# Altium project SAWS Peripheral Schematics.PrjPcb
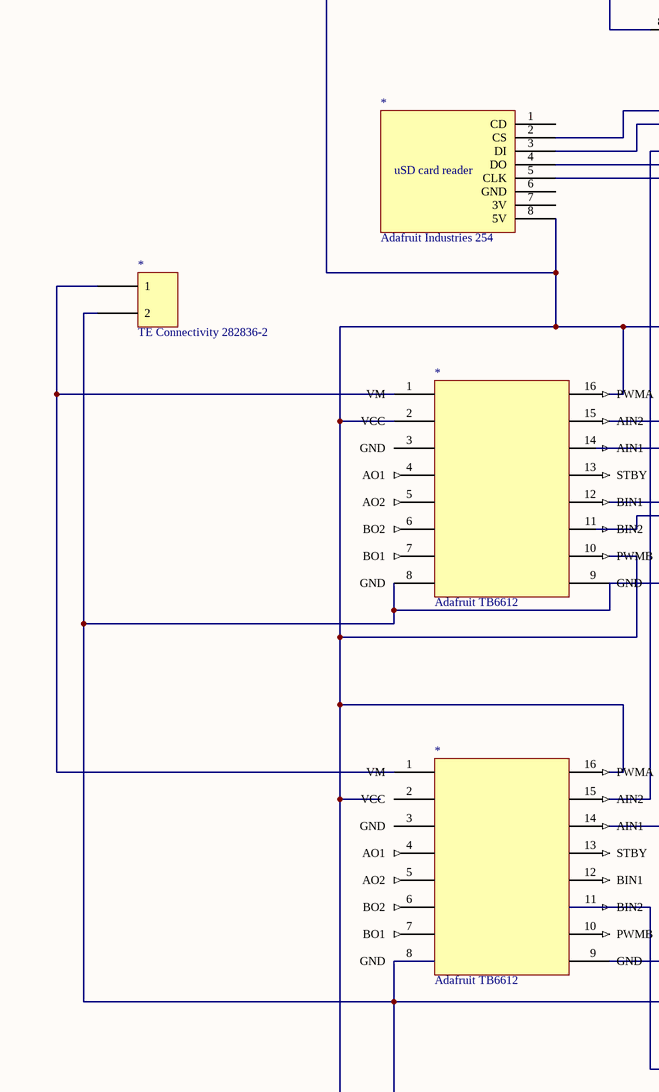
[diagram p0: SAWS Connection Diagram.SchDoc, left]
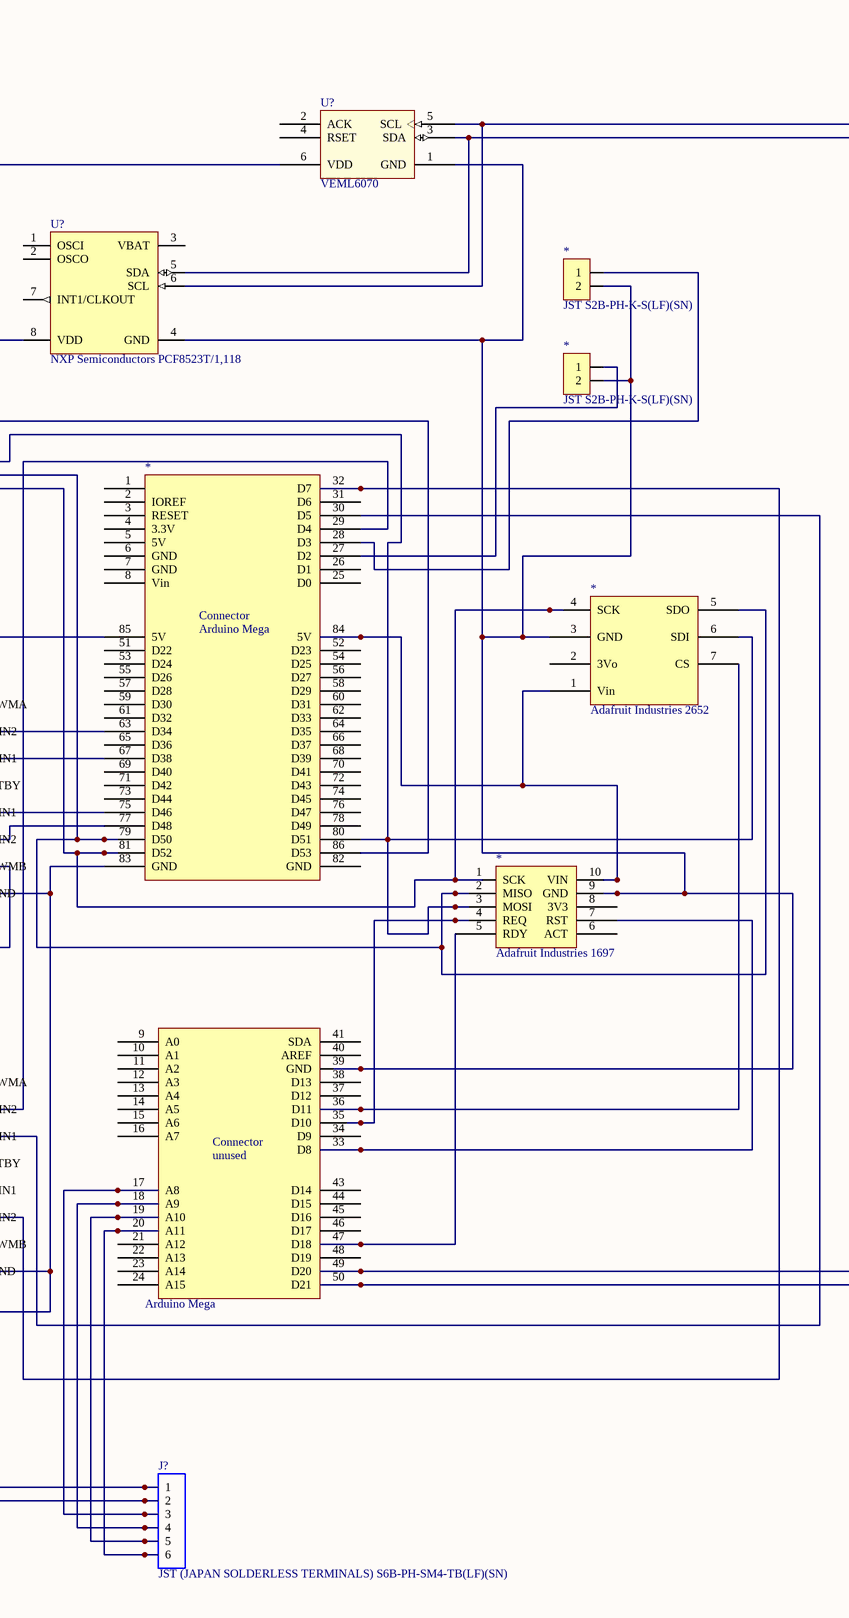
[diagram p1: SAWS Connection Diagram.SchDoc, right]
1 sheet, 12 parts. Net scope: global (net labels, ports and power ports of the same name join across sheets).

## Sheet SAWS Connection Diagram.SchDoc
size 500 x 500 mm

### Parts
(Parts that share a designator on the sheet are numbered #1, #2 ... from top to bottom, then left to right.)
*#1  JST S2B-PH-K-S(LF)(SN)  [PCBComponent_1 - duplicate]
*#2  JST S2B-PH-K-S(LF)(SN)  [PCBComponent_1 - duplicate]
*#3  Adafruit Industries 254  [PCB-14uusre4tcuerloricup-1]
*#4  TE Connectivity 282836-2  [PCB-0kdx5sneyudsmu18l6zv-1]
*#5  Adafruit Industries 2652  [PCB-8cpanwn2r2nbal49d52i-1]
*#6  Adafruit TB6612  [PCB-i53bh64vexzah4n4868h-1]
*#7  Arduino Mega  [TFT_Shield_MEGA]
*#8  Adafruit Industries 1697  [PCB-jbwx2r95ohr5pnaey095-1]
*#9  Adafruit TB6612  [PCB-i53bh64vexzah4n4868h-1]
J?  JST (JAPAN SOLDERLESS TERMINALS) S6B-PH-SM4-TB(LF)(SN)  [PCB-643062-1]
U?#1  VEML6070  [PCB-p4pozrsuowobialt3zsg-1]
U?#2  NXP Semiconductors PCF8523T/1,118  [PCB-1019860-1]

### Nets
GND: *#6.4(GND) *#6.7(GND) *#9.4(GND) *#9.7(GND)
Net*#1_1: *#1.1 *#7.28(D3)
Net*#1_2: *#1.2 *#2.2 *#5.3(GND) *#7.39(GND) *#8.9(GND) U?#1.1(GND) U?#2.4(GND)
Net*#2_1: *#2.1 *#7.27(D2)
Net*#3_2: *#3.2(CS) *#7.86(D53)
Net*#3_3: *#3.3(DI) *#5.6(SDI) *#7.80(D51) *#8.3(MOSI)
Net*#3_4: *#3.4(DO) *#5.5(SDO) *#7.79(D50) *#8.2(MISO)
Net*#3_5: *#3.5(CLK) *#5.4(SCK) *#7.81(D52) *#8.1(SCK)
Net*#3_8: *#3.8(5V) *#7.85(5V) J?.1 U?#1.6(VDD) U?#2.8(VDD)
Net*#4_2: *#4.2 *#7.83(GND) *#9.8(GND) J?.2
Net*#5_1: *#5.1(Vin) *#7.84(5V) *#8.10(VIN)
Net*#5_7: *#5.7(CS) *#7.36(D11)
Net*#7_17: *#7.17(A8) J?.3
Net*#7_18: *#7.18(A9) J?.4
Net*#7_19: *#7.19(A10) J?.5
Net*#7_20: *#7.20(A11) J?.6
Net*#7_32: *#7.32(D7) *#9.11(BIN2)
Net*#7_33: *#7.33(D8) *#8.7(RST)
Net*#7_35: *#7.35(D10) *#8.4(REQ)
Net*#7_47: *#7.47(D18) *#8.5(RDY)
Net*#7_49: *#7.49(D20) U?#1.3(SDA) U?#2.5(SDA)
Net*#7_50: *#7.50(D21) U?#1.5(SCL) U?#2.6(SCL)

Not connected (* = marked no-connect by the designer): *#3 1(CD) 6(GND) 7(3V); *#4 1; *#5 2(3Vo); *#6 1(VM) 2(VCC) 3(GND) 5(AO2) 6(BO2) 8(GND) 9(GND) 10(PWMB) 11(BIN2) 12(BIN1) 13(STBY) 14(AIN1) 15(AIN2) 16(PWMA); *#7 1 2(IOREF) 3(RESET) 4(3.3V) 5(5V) 6(GND) 7(GND) 8(Vin) 9(A0) 10(A1) 11(A2) 12(A3) 13(A4) 14(A5) 15(A6) 16(A7) 21(A12) 22(A13) 23(A14) 24(A15) 25(D0) 26(D1) 29(D4) 30(D5) 31(D6) 34(D9) 37(D12) 38(D13) 40(AREF) 41(SDA) 43(D14) 44(D15) 45(D16) 46(D17) 48(D19) 51(D22) 52(D23) 53(D24) 54(D25) 55(D26) 56(D27) 57(D28) 58(D29) 59(D30) 60(D31) 61(D32) 62(D33) 63(D34) 64(D35) 65(D36) 66(D37) 67(D38) 68(D39) 69(D40) 70(D41) 71(D42) 72(D43) 73(D44) 74(D45) 75(D46) 76(D47) 77(D48) 78(D49) 82(GND); *#8 6(ACT) 8(3V3); *#9 1(VM) 2(VCC) 3(GND) 5(AO2) 6(BO2) 9(GND) 10(PWMB) 12(BIN1) 13(STBY) 14(AIN1) 15(AIN2) 16(PWMA); U?#1 2(ACK) 4(RSET); U?#2 1(OSCI) 2(OSCO) 3(VBAT) 7(INT1/CLKOUT)

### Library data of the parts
*#1 *#2 = S2B-PH-K-S(LF)(SN): JST S2B-PH-K-S (LF)(SN) Multi-pin Connector, Angled Series PH Number of pins: 2 Nominal current: 2 A; Voltage Rating (AC): 100 V; Lead-Free Status: Lead Free; Pin Pitch: 2.00 mm; Number of Contacts: 2; Gender: Male; Insulation Resistance: 1.00 GΩ; Current Rating: 2.00 A
*#3 = 254: Roll Pin Punch 5/32 x 4-1/2 Inch Steel - GR0191303; Manufacturer Part Number: 254
*#4 = 282836-2: Wire to Board 2 Position 5 mm Pitch 30-16 AWG Euro Style Terminal Block; Current Rating: 13.5 A; Wire Gauge: 15.0 AWG; Lead-Free Status: Lead Free; Number of Positions: 2; Voltage Rating (AC): 250.0 V; Pin Pitch: 0.005 m; ELV Compliant: Compliant
*#5 = 2652: Adafruit BME280 I2C or SPI Temperature Humidity Pressure Sensor; Manufacturer Part Number: 2652
*#6 *#9 = 2448: dual dc motor driver board
*#7 = ARDUINO MEGA2560 REV3: Sainsmart, TFT LCD Mega Shield, V1.0, Arduino Mega 2560
*#8 = 1697: Micro Jack; Solder Mount Jack; Length .233; Pin Size .022-.032; Brass/Gold; Manufacturer Part Number: 1697; Output Voltage: 40.0 V; Power Rating: 200 W
J? = S6B-PH-SM4-TB(LF)(SN): CONN HEADER PH SIDE 6POS 2MM SMD; Current Rating: 2.0 A; Gender: Male; Insulation Resistance: 1000000000.0 Ω; Lead-Free Status: Lead Free; Number of Contacts: 6; Pin Pitch: 0.002 m; Voltage Rating (AC): 100.0 V
U?#1 = CMP-deee14aa07af0129-2: VEML6030 Series 5.5 V 2.35 x 1.8 x 1 mm UV A Light Sensor with I2C Interface
U?#2 = PCF8523T/1,118: IC RTC/CALENDAR 8SOIC; Lead-Free Status: Lead Free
